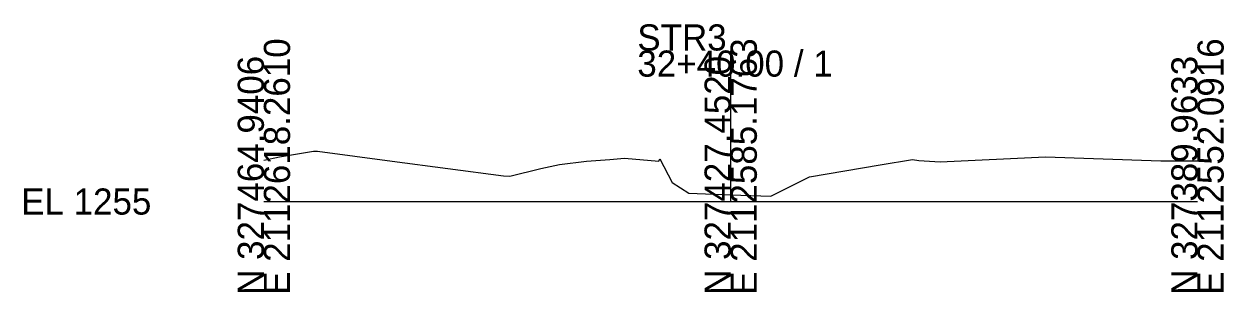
# Model space of a CAD drawing. Extents: x -26 to 103, y -10 to 14542.
# Drawn here: x -25.7 to 102.8, y 11990.3 to 12019 of the extents above; entities that cross this region are included whole.
import ezdxf

# ---------------------------------------------------------------- set-up
doc = ezdxf.new("R2010")
doc.units = 0
doc.layers.add('DESIGN - SHEET - Light Grid', color=7, linetype='Continuous')
doc.layers.add('SURVEY - GROUND - Top of Ground', color=7, linetype='Continuous')

msp = doc.modelspace()

# ---------------------------------------------------------------- linework, layer by layer
at = {"layer": 'DESIGN - SHEET - Light Grid'}
for p, q in [((50, 12000), (50, 12016.18)), ((0, 12000), (50, 12000)), ((50, 12000), (100, 12000))]:
    msp.add_line(p, q, dxfattribs=at)
at = {"layer": 'SURVEY - GROUND - Top of Ground'}
for p, q in [((1.67, 12004.8), (5.31, 12005.39)), ((5.31, 12005.39), (5.73, 12005.38)), ((5.73, 12005.38), (13.73, 12004.33)), ((0, 12004.45), (1.67, 12004.8)), ((13.73, 12004.33), (25.68, 12002.76)), ((29.68, 12003.54), (31.67, 12003.98)), ((31.67, 12003.98), (34.57, 12004.32)), ((34.57, 12004.32), (37.06, 12004.51)), ((37.06, 12004.51), (38.63, 12004.63)), ((38.63, 12004.63), (42.3, 12004.33)), ((42.3, 12004.33), (42.42, 12004.59)), ((42.42, 12004.59), (43.73, 12002.05)), ((58.46, 12002.63), (66.02, 12003.92)), ((66.02, 12003.92), (69.46, 12004.5)), ((69.46, 12004.5), (70.14, 12004.39)), ((70.14, 12004.39), (72.44, 12004.27)), ((72.44, 12004.27), (83.72, 12004.78)), ((83.72, 12004.78), (95.03, 12004.41)), ((95.03, 12004.41), (96.09, 12004.37)), ((96.09, 12004.37), (100, 12004.36)), ((25.68, 12002.76), (26.36, 12002.71)), ((26.36, 12002.71), (29.68, 12003.54)), ((54.31, 12000.56), (58.46, 12002.63)), ((43.73, 12002.05), (45.51, 12000.88)), ((45.51, 12000.88), (50, 12000.71)), ((50, 12000.71), (54.31, 12000.56))]:
    msp.add_line(p, q, dxfattribs=at)

# ---------------------------------------------------------------- texts
at = {"layer": 'DESIGN - SHEET - Light Grid'}
for s, p in [('STR3', (40, 12016.18)), ('32+40.00 / 1', (40, 12013.38)), ('EL 1255', (-26, 11998.6))]:
    msp.add_text(s, height=2.8, dxfattribs=at).set_placement(p)
for s, p in [('E 2112618.2610', (2.8, 11990)), ('E 2112585.1763', (52.8, 11990)), ('E 2112552.0916', (102.8, 11990)), ('N 327464.9406', (0, 11990)), ('N 327427.4520', (50, 11990)), ('N 327389.9633', (100, 11990))]:
    msp.add_text(s, height=2.8, rotation=90, dxfattribs=at).set_placement(p)

doc.saveas('drawing.dxf')
